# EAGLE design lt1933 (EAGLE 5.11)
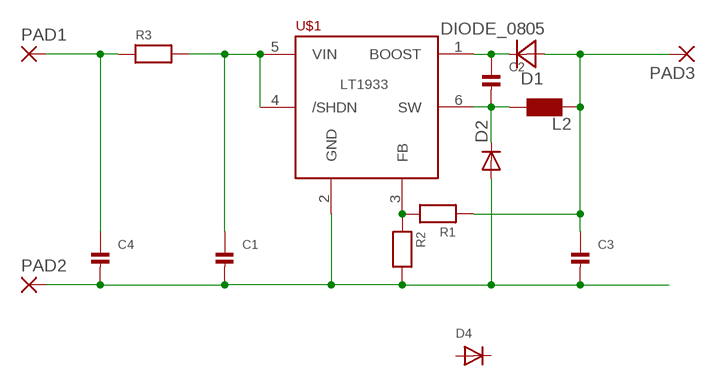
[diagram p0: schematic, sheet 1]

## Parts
C1  CAP_CERAMIC0805  [0805]
C2  CAP_CERAMIC0805  [0805]
C3  CAP_CERAMIC0805  [0805]
C4  CAP_CERAMIC0805  [0805]
D1  DIODE_0805  [DIODE_0805]
D2  DIODE-DO214AC  [DO214AC]
D4  DIODESMA  [SMADIODE]
L2  L-PISG  [PISG]
PAD1  SMD5  [SMD2,54-5,08]
PAD2  SMD5  [SMD2,54-5,08]
PAD3  SMD5  [SMD2,54-5,08]
R1  RESISTOR0805  [0805]
R2  RESISTOR0805  [0805]
R3  RESISTOR0805  [0805]
U$1  LT1933  [SOT23-6L]

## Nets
GND: C1.2 C3.2 C4.2 D2.A PAD2.1(P) R2.2 U$1.2(GND)
N$1: R1.2 R2.1 U$1.3(FB)
N$3: C1.1 R3.2 U$1.4(/SHDN) U$1.5(VIN)
N$4: C3.1 D1.2(A) L2.P$2 PAD3.1(P) R1.1
N$5: C2.2 D2.C L2.P$1 U$1.6(SW)
N$6: C2.1 D1.1(C) U$1.1(BOOST)
N$7: C4.1 PAD1.1(P) R3.1
Unconnected: D4.A D4.C

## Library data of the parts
C1-C4 = microbuilder:CAP_CERAMIC: Ceramic Capacitors
D1 = seb:DIODE_0805
D2 = diode:DIODE-: DIODE
D4 = microbuilder:DIODE: Diode
L2 = seb:L-PISG
PAD1-PAD3 = wirepad:SMD5: SMD PAD
R1-R3 = microbuilder:RESISTOR: Resistors
U$1 = seb:LT1933

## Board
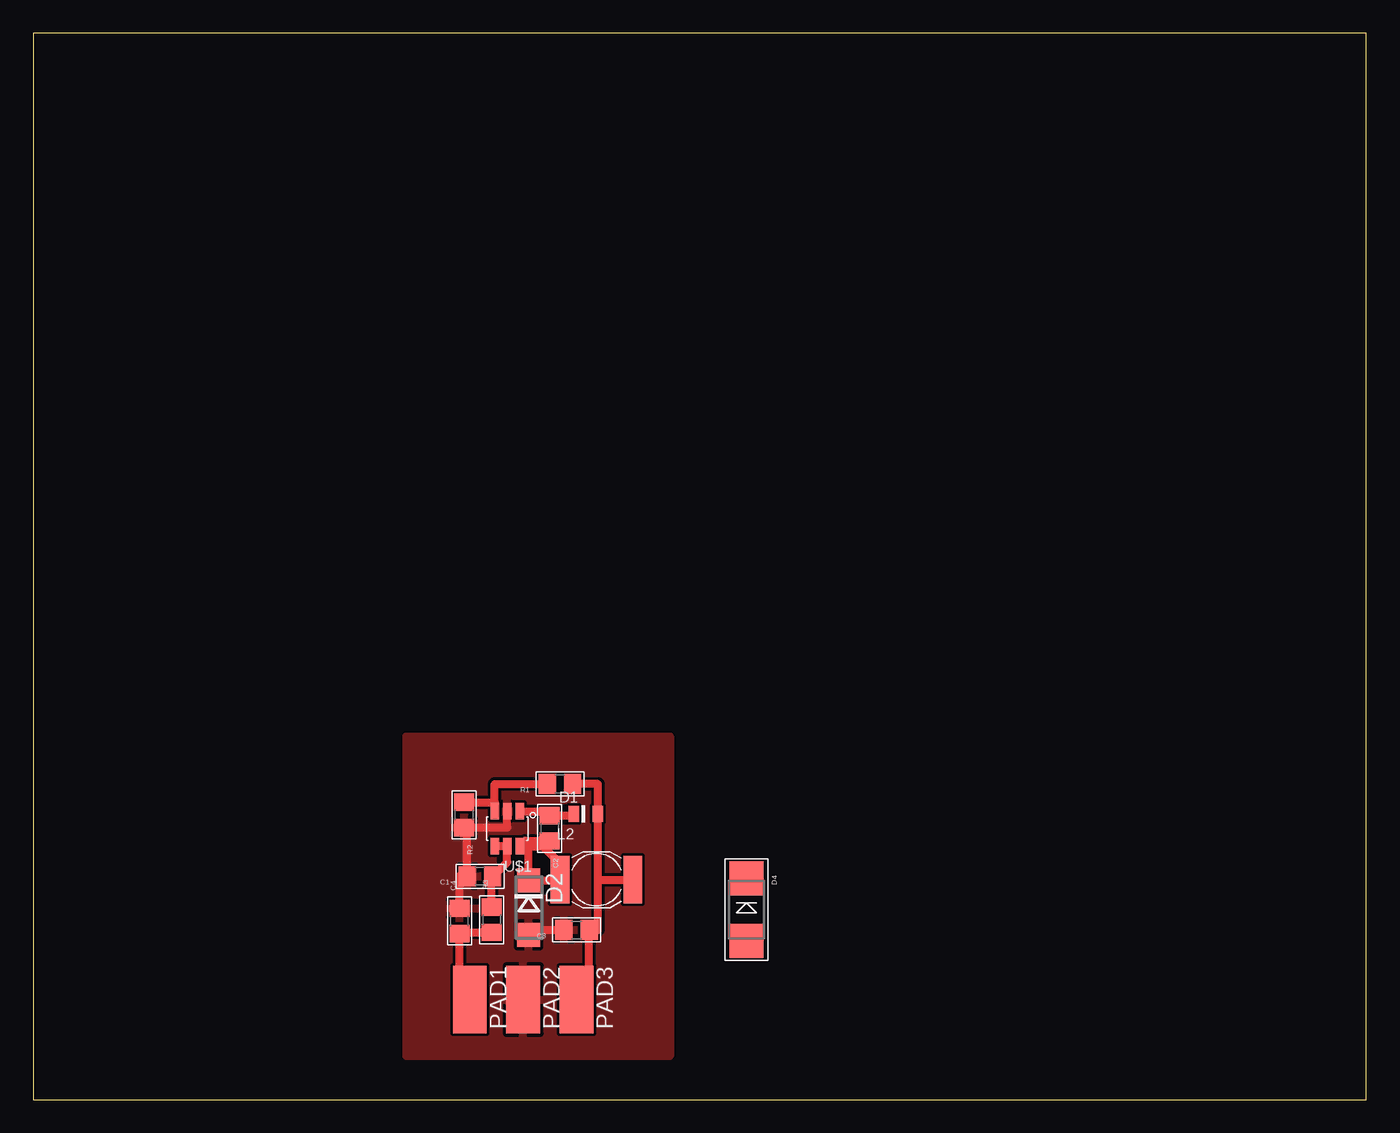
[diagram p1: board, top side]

Size 100 x 80 mm. Coordinates in mm from the lower left corner, seen from the top.
Outline: 0,0 100,0 100,80 0,80 0,0
Copper layers (1*16): Top 0.035mm / dielectric 1.5mm / Bottom 0.035mm
Design rules "default": minimum track width 10mil, minimum drill 24mil, track to track 8mil, track to pad 8mil, pad to pad 8mil, via to via 8mil, smd to smd 8mil, copper to edge 40mil, drill to drill 8mil, minimum pad ring 10mil, minimum via ring 8mil, stop-mask expansion 4mil, vias tented up to drill 0mil, thermal gap 10mil

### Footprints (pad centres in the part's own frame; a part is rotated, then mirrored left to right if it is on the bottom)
0805 = smd 1.3 x 1.5: 1 -0.95,0; 2 0.95,0
DIODE_0805 = smd 0.8 x 1.2: 1 -0.9,0; 2 0.9,0
DO214AC = smd 1.8 x 1.7: A 2.05,0; C -2.05,0
SMADIODE = smd 2.54 x 2.54: A 2.349,0; C -2.349,0
PISG = smd 1.4 x 3.56: P$1 -2.73,0; P$2 2.73,0
SMD2,54-5,08 = smd 2.54 x 5.08: 1 0,0
SOT23-6L = smd 0.63 x 1.22: 1 -0.95,-1.31; 2 0,-1.31; 3 0.95,-1.31; 4 0.95,1.31; 5 0,1.31; 6 -0.95,1.31

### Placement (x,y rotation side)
C1  33.51,16.76 180 top
C2  38.74,20.36 270 top
C3  40.76,12.72 180 top
C4  31.97,13.39 90 top
D1  41.45,21.43 0 top
D2  37.16,14.4 270 top
D4  53.5,14.25 270 top
L2  42.25,16.5 0 top
PAD1  32.75,7.5 180 top
PAD2  36.75,7.5 180 top
PAD3  40.75,7.5 180 top
R1  39.51,23.68 180 top
R2  32.32,21.36 270 top
R3  34.39,13.49 90 top
U$1  35.56,20.32 180 top

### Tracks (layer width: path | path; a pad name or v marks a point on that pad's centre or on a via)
GND
  Top 0.61: U$1.2 35.56,20.41 R2.2 32.56,20.41 C1.2 31.97,16.76 C4.2 | C3.2 37.16,12.72 D2.A
  pour Top: 28,27.25 47.75,27.25 47.75,3.25 28,3.25
N$1
  Top 0.61: R2.1 34.61,22.31 U$1.3 34.61,23.68 R1.2
N$3
  Top 0.61: R3.2 34.39,16.76 C1.1 34.74,16.99 35.56,17.81 U$1.5 U$1.4
N$4
  Top 0.61: R1.1 42.35,23.68 D1.2 42.35,16.5 | 42.35,16.5 42.35,12.72 C3.1 41.71,7.5 PAD3.1 | 42.35,16.5 L2.P$2
N$5
  Top 0.61: 37.16,19.01 U$1.6 | 37.16,19.01 D2.C 39.91,16.45 39.91,16.5 L2.P$1 | 36.91,19.41 37.9,19.41 | 37.16,19.01 36.91,19.41 | 39.71,17.52 37.9,19.33 37.9,19.41 | 37.16,19.01 38.16,19.01 | 37.9,19.41 C2.2 | 36.91,19.41 36.91,18.7
N$6
  Top 0.61: U$1.1 38.74,21.63 C2.1 40.55,21.31 D1.1
N$7
  Top 0.61: R3.1 31.97,12.54 C4.1 31.97,7.5 PAD1.1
